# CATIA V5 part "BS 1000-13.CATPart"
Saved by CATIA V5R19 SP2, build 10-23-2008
Part number: BS 1000-13
Bounding box of the stored display mesh (mm): x -24.865 to 24.865, y -24.997 to 24.997, z 0 to 64
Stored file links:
  C:\Users\Bora\Desktop\3D Katı model\BS serisi\BS 1000\BS 1000-13.CATPart
  C:\Program Files\Dassault Systemes\B19\intel_a\reffiles\standard\MetricThickPitch.txt
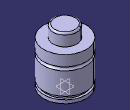
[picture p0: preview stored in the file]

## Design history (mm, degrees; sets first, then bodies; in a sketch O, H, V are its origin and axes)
Body1 (main body)
  Sketch1 on yz-plane, origin (0, 0, 0), H (0, 1, 0), V (0, 0, 1)
    point P2 (14, 62)
    line L1 (14, 62) -> (14, 50)
    point P3 (25, 37.5)
    line L2 (25, 50) -> (25, 37.5)
    point P6 (25, 33.5)
    line L3 (25, 33.5) -> (25, 7.5)
    line L4 (25, 4) -> (25, 0)
    point P9 (25, 33.5)
    point P10 (25, 37.5)
    arc A1 centre (25, 35.5) radius 2 from (25, 37.5) to (25, 33.5) ccw
    point P12 (14, 62)
    arc A2 centre (12, 62) radius 2 from (14, 62) to (12, 64) ccw
    point P13 (22.5, 4)
    point P14 (22.5, 4)
    line L5 (22.5, 7.5) -> (22.5, 4)
    line L6 (12, 64) -> (0, 64)
    point P16 (0, 64)
    line L7 (14, 50) -> (25, 50)
    line L8 (22.5, 7.5) -> (25, 7.5)
    line L9 (0, 0) -> (25, 0)
    line L10 (22.5, 4) -> (25, 4)
    tangency: L6 A2
    coincidence: P16 V, P2 P12, P3 P10, P6 P9, P13 P14
    horizontal: L7 H, L8 H, L9 H, L10 H
  Shaft1: profile Sketch1, axis Sketch1.V, angle 360
  Sketch2 on face of Shaft1 from Sketch1.L9, origin (0, 0, 0), H (1, 0, 0), V (0, -1, 0)
    point P1 (10, 0)
    distance P1 V = 10
  Hole1: placed by Sketch2, at (10, 0, 0) direction (0, 0, 1), diameter 6.647, depth 6, threaded "M8", thread diameter 8, thread depth 6, pitch 1.25
  CircPattern1: of Hole1, instances 2, angular step 180, axis from xy-plane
